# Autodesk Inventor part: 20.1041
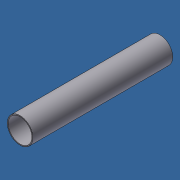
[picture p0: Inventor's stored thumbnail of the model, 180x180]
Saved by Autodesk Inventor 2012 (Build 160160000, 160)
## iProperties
Created: 2007-07
Part Number: 20.1041
Material: Aluminum-6061
Document SubType Name: Modeling
Designer: Andy Moles
Mass: 222.31 g
Surface Area: 826.365 cm^2
Volume: 82.0333 cm^3
Density: 2.71 g/cm^3
Description: TUBE AL 50 X 2 L = SPECIFY
Vendor: F
Author: Andy Moles
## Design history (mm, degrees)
sketch "Sketch1"
  geometry: C1 r 23 at (0, 0); C2 r 25 at (0, 0); 1 further point
  constraints: 2 centre point, 2 coincident
  dimensions: "d0" = 46 diameter of C1; "d1" = 50 diameter of C2
extrude "Extrusion1" new body sketch "Sketch1" stored distance "d2" = 272 (= AL_TUBE); taper "d3" = 0 deg
body "Solid1"
other parameters: "AL_TUBE" = 272 (computed from FRAME_ID) [user parameter; used in 1 equation term]
